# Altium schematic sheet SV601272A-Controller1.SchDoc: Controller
size 431 x 279 mm; Date: Not shown in title block; ApprovedBy: Not shown in title block; CheckedBy: Not shown in title block; Author: Not shown in title block; CompanyName: Not shown in title block; Engineer: Not shown in title block; Organization: Not shown in title block; Address1: Not shown in title block; Address2: Not shown in title block; Address3: Not shown in title block; Address4: Not shown in title block; DocumentNumber: 4; Revision: Use project parameter SCH_Rev; SheetNumber: 4; SheetTotal: 11; PageSetup: Record=PageOptions¦CenterHorizontal=True¦CenterVertical=True¦PrintScale=1.00¦XCorrection=1.00¦YCorrection=1.00¦PrintKind=0¦BorderSize=5000000¦LeftOffset=0¦BottomOffset=0¦Orientation=2¦PaperLength=1000¦PaperWidth=1000¦Scale=100¦PaperSource=15¦PrintQuality=600¦MediaType=1¦DitherType=10¦PaperKind=Letter¦PrintScaleMode=1
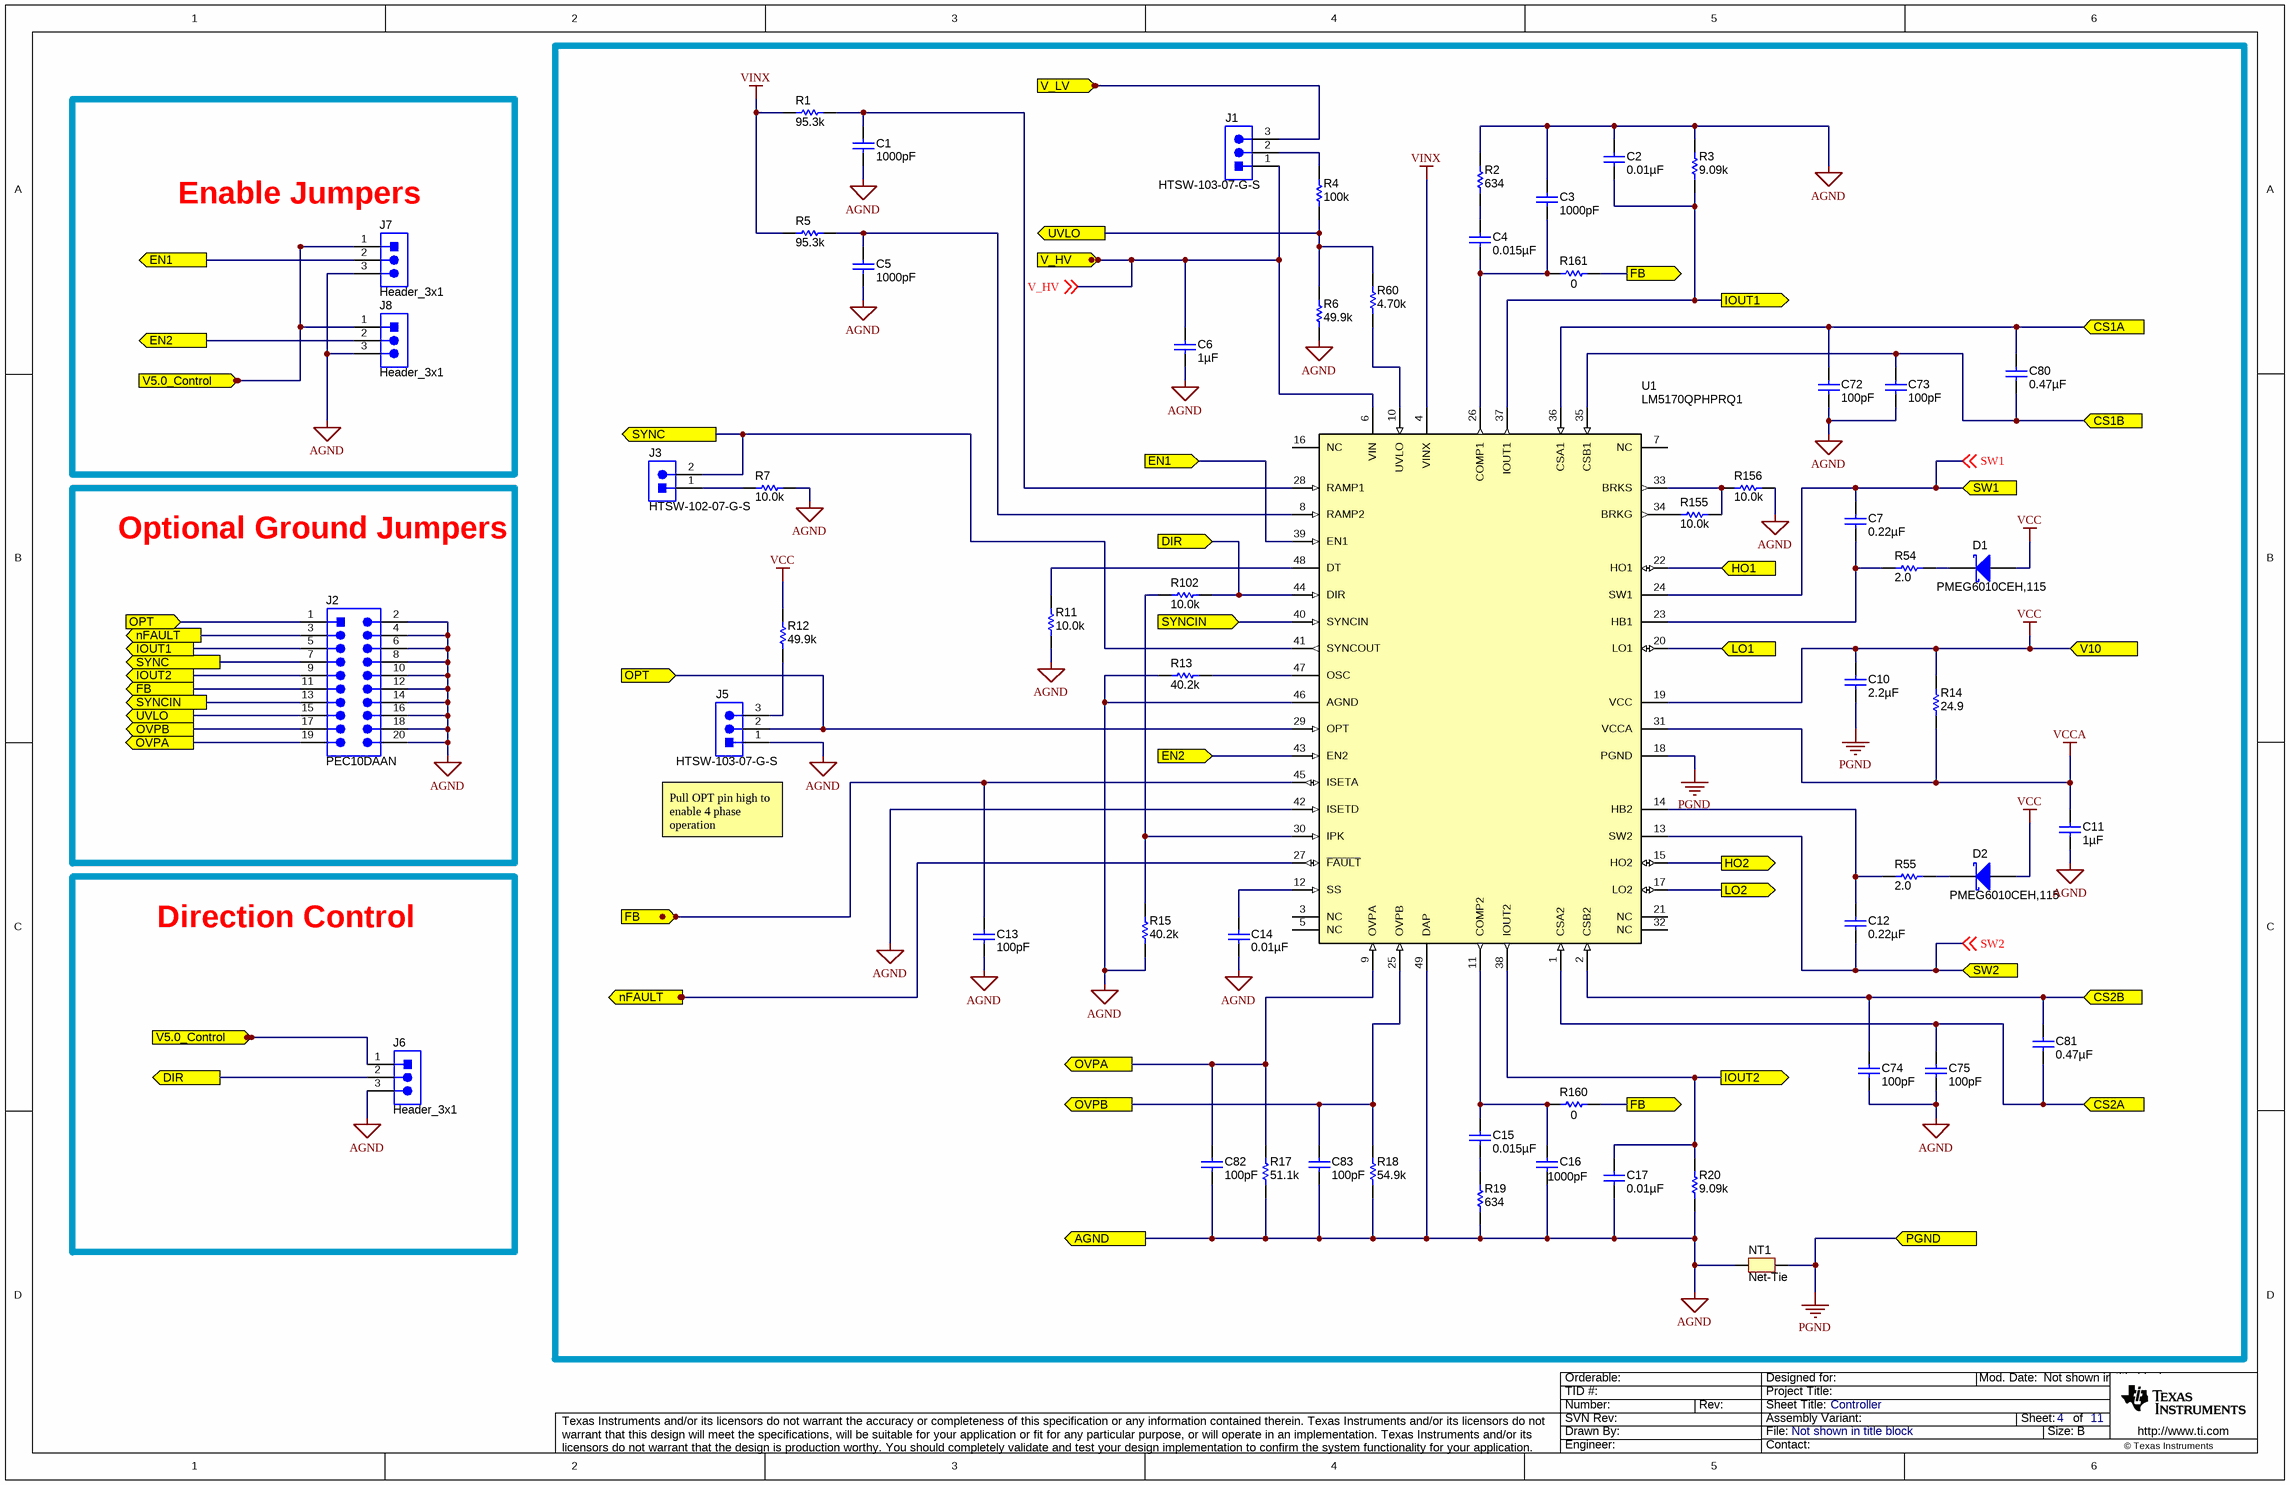
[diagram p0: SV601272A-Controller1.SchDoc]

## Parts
C1  ValueDisplayed: 1000pF  [0603L]  (hidden comment: C1608C0G2A102J080AA)
C2  ValueDisplayed: 0.01µF  [0603L]  (hidden comment: 06031C103KAT2A)
C3  ValueDisplayed: 1000pF  [0603L]  (hidden comment: C1608C0G2A102J080AA)
C4  ValueDisplayed: 0.015µF  [0603L]  (hidden comment: GRM188R71E153KA01D)
C5  ValueDisplayed: 1000pF  [0603L]  (hidden comment: C1608C0G2A102J080AA)
C6  ValueDisplayed: 1µF  [0805_HV]  (hidden comment: C2012X7S2A105K125AB)
C7  ValueDisplayed: 0.22µF  [0603L]  (hidden comment: C1608X7R1H224K080AB)
C10  ValueDisplayed: 2.2µF  [0805_HV]  (hidden comment: C2012X7R1C225K125AB)
C11  ValueDisplayed: 1µF  [0603L]  (hidden comment: GRM188R71E105KA12D)
C12  ValueDisplayed: 0.22µF  [0603L]  (hidden comment: C1608X7R1H224K080AB)
C13  ValueDisplayed: 100pF  [0603L]  (hidden comment: C0603C101J5GACTU)
C14  ValueDisplayed: 0.01µF  [0603L]  (hidden comment: 06031C103KAT2A)
C15  ValueDisplayed: 0.015µF  [0603L]  (hidden comment: GRM188R71E153KA01D)
C16  ValueDisplayed: 1000pF  [0603L]  (hidden comment: C1608C0G2A102J080AA)
C17  ValueDisplayed: 0.01µF  [0603L]  (hidden comment: 06031C103KAT2A)
C72  ValueDisplayed: 100pF  [0603L]  (hidden comment: C0603C101J5GACTU)
C73  ValueDisplayed: 100pF  [0603L]  (hidden comment: C0603C101J5GACTU)
C74  ValueDisplayed: 100pF  [0603L]  (hidden comment: C0603C101J5GACTU)
C75  ValueDisplayed: 100pF  [0603L]  (hidden comment: C0603C101J5GACTU)
C80  ValueDisplayed: 0.47µF  [0603L]  (hidden comment: GRM188R71C474KA88D)
C81  ValueDisplayed: 0.47µF  [0603L]  (hidden comment: GRM188R71C474KA88D)
C82  ValueDisplayed: 100pF  [0603L]  (hidden comment: C0603C101J5GACTU)
C83  ValueDisplayed: 100pF  [0603L]  (hidden comment: C0603C101J5GACTU)
D1  PMEG6010CEH,115  [SOD-123F]
D2  PMEG6010CEH,115  [SOD-123F]
J1  HTSW-103-07-G-S  [Samtec_HTSW-103-07-G-S]
J2  PEC10DAAN  [SULLINS_PEC10DAAN]
J3  HTSW-102-07-G-S  [Samtec_HTSW-102-07-G-S]
J5  HTSW-103-07-G-S  [Samtec_HTSW-103-07-G-S]
J6  Header_3x1  [Samtec_HTSW-103-07-G-S]
J7  Header_3x1  [Samtec_HTSW-103-07-G-S]
J8  Header_3x1  [Samtec_HTSW-103-07-G-S]
NT1  Net-Tie  [Net-Tie_10mil]  (net tie, no BOM)
R1  ValueDisplayed: 95.3k  [0603L]  (hidden comment: CRCW060395K3FKEA)
R2  ValueDisplayed: 634  [0603L]  (hidden comment: CRCW0603634RFKEA)
R3  ValueDisplayed: 9.09k  [0603L]  (hidden comment: CRCW06039K09FKEA)
R4  ValueDisplayed: 100k  [0603]  (hidden comment: CRCW0603100KFKEA)
R5  ValueDisplayed: 95.3k  [0603L]  (hidden comment: CRCW060395K3FKEA)
R6  ValueDisplayed: 49.9k  [0603]  (hidden comment: ERJ-3EKF4992V)
R7  ValueDisplayed: 10.0k  [0603L]  (hidden comment: CRCW060310K0FKEA)
R11  ValueDisplayed: 10.0k  [0603L]  (hidden comment: CRCW060310K0FKEA)
R12  ValueDisplayed: 49.9k  [0603L]  (hidden comment: CRCW060349K9FKEA)
R13  ValueDisplayed: 40.2k  [0603L]  (hidden comment: CRCW060340K2FKEA)
R14  ValueDisplayed: 24.9  [0805L]  (hidden comment: CRCW080524R9FKEA)
R15  ValueDisplayed: 40.2k  [0603]  (hidden comment: ERJ-3EKF4022V)
R17  ValueDisplayed: 51.1k  [0603L]  (hidden comment: CRCW060351K1FKEA)
R18  ValueDisplayed: 54.9k  [0603L]  (hidden comment: CRCW060354K9FKEA)
R19  ValueDisplayed: 634  [0603L]  (hidden comment: CRCW0603634RFKEA)
R20  ValueDisplayed: 9.09k  [0603L]  (hidden comment: CRCW06039K09FKEA)
R54  ValueDisplayed: 2.0  [0805_HV]  (hidden comment: CRCW08052R00JNEA)
R55  ValueDisplayed: 2.0  [0805_HV]  (hidden comment: CRCW08052R00JNEA)
R60  ValueDisplayed: 4.70k  [0603]  (hidden comment: RC0603FR-074K7L)
R102  ValueDisplayed: 10.0k  [0603L]  (hidden comment: CRCW060310K0FKEA)
R155  ValueDisplayed: 10.0k  [0603]  (hidden comment: ERJ-3EKF1002V)
R156  ValueDisplayed: 10.0k  [0603]  (hidden comment: ERJ-3EKF1002V)
R160  ValueDisplayed: 0  [0603]  (hidden comment: Resistor)
R161  ValueDisplayed: 0  [0603]  (hidden comment: Resistor)
U1  LM5170QPHPRQ1  [PHP0048D_L]

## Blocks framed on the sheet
Enable Jumpers: J7 J8
Optional Ground Jumpers: J2
Direction Control: J6

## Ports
AGND, CS1A, CS1B, CS2A, CS2B, DIR, EN1, EN2, FB, HO1, HO2, IOUT1, IOUT2, LO1, LO2, nFAULT, OPT, OVPA, OVPB, PGND, SW1, SW2, SYNC, SYNCIN, UVLO, V5.0_Control, V10, V_HV, V_LV

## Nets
AGND: C1.2 C2.1 C3.1 C5.2 C6.2 C11.2 C13.2 C14.2 C16.2 C17.2 C72.2 C73.2 C74.2 C75.2 C82.2 C83.2 J2.2 J2.4 J2.6 J2.8 J2.10 J2.12 J2.14 J2.16 J2.18 J2.20 J5.1 J6.3 J7.3 J8.3 NT1.1 R2.2 R3.2 R6.1 R7.2 R11.1 R13.1 R15.1 R17.1 R18.1 R19.1 R20.1 R156.1 U1.42(ISETD) U1.46(AGND) U1.49(DAP) ; port AGND
PGND: C10.2 NT1.2 U1.18(PGND) ; port PGND
VCC: C10.1 D1.2(A) D2.2(A) R12.2 R14.2 U1.19(VCC) ; port V10
VCCA: C11.1 R14.1 U1.31(VCCA)
VINX: R1.1 R5.1 U1.4(VINX)
CS1A: C72.1 C80.1 U1.36(CSA1) ; port CS1A
CS1B: C73.1 C80.2 U1.35(CSB1) ; port CS1B
CS2A: C75.1 C81.2 U1.1(CSA2) ; port CS2A
CS2B: C74.1 C81.1 U1.2(CSB2) ; port CS2B
DIR: J6.2 R102.2 U1.44(DIR) ; port DIR
EN1: J7.2 U1.39(EN1) ; port EN1
EN2: J8.2 U1.43(EN2) ; port EN2
FB: C13.1 J2.11 R160.2 R161.2 U1.45(ISETA) ; port FB
HO1: U1.22(HO1) ; port HO1
HO2: U1.15(HO2) ; port HO2
IOUT1: C2.2 J2.5 R3.1 U1.37(IOUT1) ; port IOUT1
IOUT2: C17.1 J2.9 R20.2 U1.38(IOUT2) ; port IOUT2
LO1: U1.20(LO1) ; port LO1
LO2: U1.17(LO2) ; port LO2
nFAULT: J2.3 U1.27(~{FAULT}) ; port nFAULT
OPT: J2.1 J5.2 U1.29(OPT) ; port OPT
OVPA: C82.1 J2.19 R17.2 U1.9(OVPA) ; port OVPA
OVPB: C83.1 J2.17 R18.2 U1.25(OVPB) ; port OVPB
SW1: C7.1 U1.24(SW1) ; off-sheet SW1, port SW1
SW2: C12.2 U1.13(SW2) ; off-sheet SW2, port SW2
SYNC: J2.7 J3.2 U1.41(SYNCOUT) ; port SYNC
SYNCIN: J2.13 U1.40(SYNCIN) ; port SYNCIN
UVLO: J2.15 R4.1 R6.2 R60.2 ; port UVLO
V5.0_Control: J6.1 J7.1 J8.1 ; port V5.0_Control
V_HV: C6.1 J1.1 U1.6(VIN) ; off-sheet V_HV, port V_HV
V_LV: J1.3 ; port V_LV
NetC1_1: C1.1 R1.2 U1.28(RAMP1)
NetC3_2: C3.2 C4.2 R161.1 U1.26(COMP1)
NetC4_1: C4.1 R2.1
NetC5_1: C5.1 R5.2 U1.8(RAMP2)
NetC7_2: C7.2 R54.1 U1.23(HB1)
NetC12_1: C12.1 R55.1 U1.14(HB2)
NetC14_1: C14.1 U1.12(SS)
NetC15_1: C15.1 C16.1 R160.1 U1.11(COMP2)
NetC15_2: C15.2 R19.2
NetD1_1: D1.1(K) R54.2
NetD2_1: D2.1(K) R55.2
NetJ1_2: J1.2 R4.2
NetJ3_1: J3.1 R7.1
NetJ5_3: J5.3 R12.1
NetR11_2: R11.2 U1.48(DT)
NetR13_2: R13.2 U1.47(OSC)
NetR15_2: R15.2 R102.1 U1.30(IPK)
NetR60_1: R60.1 U1.10(UVLO)
NetR155_1: R155.1 R156.2 U1.33(BRKS)
NetR155_2: R155.2 U1.34(BRKG)

Not connected (* = marked no-connect by the designer): U1 3(NC) 5(NC) 7(NC) 16(NC) 21(NC) 32(NC)

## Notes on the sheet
- (near J5) Pull OPT pin high to enable 4 phase operation

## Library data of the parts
C1 C3 C5 C16 = C1608C0G2A102J080AA: CAP, CERM, 1000 pF, 100 V, +/- 5%, C0G/NP0, 0603; Manufacturer: TDK; Polarized: N; CompType: Capacitor; Value: 1000pF; U/M: EA; Cap_F: 0.000000001; Tolerance_%: 5; ESR_ohm: 0.0589; Value1: 0.0589 ohm; VDC_V: 100; Value2: 100V; TaMin_C: -55; TaMax_C: 125; Cap_Case: 0603; AEC Category: Q200
C2 C14 C17 = 06031C103KAT2A: CAP, CERM, 0.01 µF, 100 V, +/- 10%, X7R, 0603; Manufacturer: AVX; Polarized: N; CompType: Capacitor; Value: 0.01uF; U/M: EA; Cap_F: 0.00000001; Tolerance_%: 10; ESR_ohm: 0.098; Value1: 0.098 ohm; VDC_V: 100; Value2: 100V; TaMin_C: -55; TaMax_C: 125; Cap_Case: 0603
C4 C15 = GRM188R71E153KA01D: CAP, CERM, 0.015 µF, 25 V, +/- 10%, X7R, 0603; Manufacturer: MuRata; Polarized: N; CompType: Capacitor; Value: 0.015uF; U/M: EA; Cap_F: 0.000000015; Tolerance_%: 10; Value1: Unknown; VDC_V: 25; Value2: 25V; TaMin_C: -55; TaMax_C: 125; Cap_Case: 0603
C6 = C2012X7S2A105K125AB: CAP, CERM, 1 µF, 100 V, +/- 10%, X7S, 0805; Manufacturer: TDK; Polarized: N; CompType: Capacitor; Value: 1uF; U/M: EA; Cap_F: 0.000001; Tolerance_%: 10; Value1: Unknown; VDC_V: 100; Value2: 100V; TaMin_C: -55; TaMax_C: 125; Cap_Case: 0805; AEC Category: Q200
C7 C12 = C1608X7R1H224K080AB: CAP, CERM, 0.22 µF, 50 V, +/- 10%, X7R, 0603; Manufacturer: TDK; Polarized: N; CompType: Capacitor; Value: 0.22uF; U/M: EA; Cap_F: 0.00000022; Tolerance_%: 10; Value1: Unknown; VDC_V: 50; Value2: 50V; TaMin_C: -55; TaMax_C: 125; Cap_Case: 0603
C10 = C2012X7R1C225K125AB: CAP, CERM, 2.2 µF, 16 V, +/- 10%, X7R, 0805; Manufacturer: TDK; CompType: Capacitor; Value: 2.2uF; U/M: EA; Tolerance_%: 10; VDC_V: 16; Polarized: N; Cap_F: 0.0000022; ESR_ohm: 0.0049; Value1: 0.0049 ohm; Value2: 16V; TaMin_C: -55; TaMax_C: 125; Cap_Case: 0805; AEC Category: Q200
C11 = GRM188R71E105KA12D: CAP, CERM, 1 µF, 25 V, +/- 10%, X7R, 0603; Manufacturer: MuRata; Polarized: N; CompType: Capacitor; Value: 1uF; U/M: EA; Cap_F: 0.000001; Tolerance_%: 10; Value1: Unknown; VDC_V: 25; Value2: 25V; TaMin_C: -55; TaMax_C: 125; Cap_Case: 0603
C13 = C0603C101J5GACTU: CAP, CERM, 100 pF, 50 V, +/- 5%, C0G/NP0, 0603; Manufacturer: Kemet; Polarized: N; CompType: Capacitor; Value: 100pF; U/M: EA; Cap_F: 0.0000000001; Tolerance_%: 5; Value1: Unknown; VDC_V: 50; Value2: 50V; TaMin_C: -55; TaMax_C: 125; Cap_Case: 0603; AEC Category: Q200; SizeArea_mm2: 1.28; SizeAreaWB_mm2: 4.68; SizeX_mm: 1.6; SizeY_mm: 0.8; SizeZ_mm: 1
C72-C75 C82 C83 = C0603C101J5GACTU: CAP, CERM, 100 pF, 50 V, +/- 5%, C0G/NP0, 0603; Manufacturer: Kemet; Polarized: N; CompType: Capacitor; Value: 100pF; U/M: EA; Cap_F: 0.0000000001; Tolerance_%: 5; Value1: Unknown; VDC_V: 50; Value2: 50V; TaMin_C: -55; TaMax_C: 125; Cap_Case: 0603; AEC Category: Q200
C80 C81 = GRM188R71C474KA88D: CAP, CERM, 0.47 µF, 16 V, +/- 10%, X7R, 0603; Manufacturer: MuRata; Polarized: N; CompType: Capacitor; Value: 0.47uF; U/M: EA; Cap_F: 0.00000047; Tolerance_%: 10; Value1: Unknown; VDC_V: 16; Value2: 16V; TaMin_C: -55; TaMax_C: 125; Cap_Case: 0603; AEC Category: Q200
D1 D2 = PMEG6010CEH,115: Diode, Schottky, 60 V, 1 A, SOD-123F; Manufacturer: NXP Semiconductor; U/M: EA; Vf_V: 0.57; Value: 60V; Value1: 1A; Value2: 0.57V; Io_A: 1; Vr_V: 60; TJmax_C: 150
J1 J5 = HTSW-103-07-G-S: Header, 100mil, 3x1, Gold, TH; Manufacturer: Samtec; SymbolCreator: a0799628; U/M: EA
J2 = CMP-0054623-1: Header, 2.54mm, 10x2, Tin, TH; Manufacturer: Sullins Connector Solutions; CNHeader: TRUE; Current_A: 3A; Green_Lifecycle: Not Set; Shrouded: N; Gender: Male; Green_REACh: Incomplete; Row_Count: 2; RowSpacing_mm: 2.54; CT: FALSE; Cert_UL: Y
J3 = HTSW-102-07-G-S: Header, 100mil, 2x1, Gold, TH; Manufacturer: Samtec; SymbolCreator: a0412235; U/M: EA
J6-J8 = CMP-0075484-1: Header, 100mil, 3x1, Gold, TH; PartNumber: HTSW-103-07-G-S; Manufacturer: Samtec; CNHeader: True; CT: False; Green_Lifecycle: Active; Green_REACh: Passed
NT1 = Net-Tie: Single point connection between nets.; SymbolCreator: codlsc
R1 R5 = CRCW060395K3FKEA: RES, 95.3 k, 1%, 0.1 W, 0603; Manufacturer: Vishay-Dale; CompType: Resistor; Value: 95.3k; Res_ohm: 95300; Value_Code: 95k3; Tolerance_%: 1; Power_W: 0.1; Value2: 0.1W; VDC_V: 75; TempCo: 100 ppm/C; EIA_Code: E96; U/M: EA
R2 R19 = CRCW0603634RFKEA: RES, 634, 1%, 0.1 W, 0603; Manufacturer: Vishay-Dale; CompType: Resistor; Value: 634; Value_Code: 634R; Tolerance_%: 1; Power_W: 0.1; Value2: 0.1W; VDC_V: 75; TempCo: 100 ppm/C; EIA_Code: E96; U/M: EA
R3 R20 = CRCW06039K09FKEA: RES, 9.09 k, 1%, 0.1 W, 0603; Manufacturer: Vishay-Dale; CompType: Resistor; Value: 9.09k; Res_ohm: 9090; Value_Code: 9k09; Tolerance_%: 1; Power_W: 0.1; Value2: 0.1W; VDC_V: 75; TempCo: 100 ppm/C; EIA_Code: E96; U/M: EA
R4 = CMP-0021990-4: RES, 100 k, 1%, 0.1 W, AEC-Q200 Grade 0, 0603; Manufacturer: Vishay-Dale; Power_W: 100mW; TempCo: 100 ppm/C; Value: 100k; EIA_Code: E96; SizeX_mm: 1.6; SizeY_mm: 0.8; SizeZ_mm: 1; Value2: 0.1W; SizeArea_mm2: 1.28; CompType: Resistor; AEC Qualified: Y; VDC_V: 75V; AEC Category: Q200; AEC Grade: 0
R6 = CMP-0022705-3: RES, 49.9 k, 1%, 0.1 W, AEC-Q200 Grade 0, 0603; Manufacturer: Panasonic; Power_W: 100mW; TempCo: 100 ppm/C; Value_Code: 49k9; U/M: EA; Value: 49.9k; EIA_Code: E96; SizeX_mm: 1.6; SizeY_mm: 0.8; SizeZ_mm: 1; Value2: 0.1W; SizeArea_mm2: 1.28; CompType: Resistor; AEC Qualified: Y; VDC_V: 75V; AEC Grade: 0; AEC Category: Q200
R7 R102 = CRCW060310K0FKEA: RES, 10.0 k, 1%, 0.1 W, 0603; Manufacturer: Vishay-Dale; CompType: Resistor; Value: 10.0k; Res_ohm: 10000; Value_Code: 10k0; Tolerance_%: 1; Power_W: 0.1; Value2: 0.1W; VDC_V: 75; TempCo: 100 ppm/C; EIA_Code: E96; U/M: EA
R11 = CRCW060310K0FKEA: RES, 10.0 k, 1%, 0.1 W, 0603; Manufacturer: Vishay-Dale; CompType: Resistor; Value: 10.0k; Res_ohm: 10000; Value_Code: 10k0; Tolerance_%: 1; Power_W: 0.1; Value2: 0.1W; VDC_V: 75; TempCo: 100 ppm/C; EIA_Code: E96; U/M: EA; SizeArea_mm2: 1.28; SizeX_mm: 1.6; SizeY_mm: 0.8; AEC Category: Q200
R12 = CRCW060349K9FKEA: RES, 49.9 k, 1%, 0.1 W, 0603; Manufacturer: Vishay-Dale; CompType: Resistor; Value: 49.9k; Res_ohm: 49900; Value_Code: 49k9; Tolerance_%: 1; Power_W: 0.1; Value2: 0.1W; VDC_V: 75; TempCo: 100 ppm/C; EIA_Code: E96; U/M: EA
R13 = CRCW060340K2FKEA: RES, 40.2 k, 1%, 0.1 W, 0603; Manufacturer: Vishay-Dale; CompType: Resistor; Value: 40.2k; Res_ohm: 40200; Value_Code: 40k2; Tolerance_%: 1; Power_W: 0.1; Value2: 0.1W; VDC_V: 75; TempCo: 100 ppm/C; EIA_Code: E96; U/M: EA; SizeArea_mm2: 1.28; SizeX_mm: 1.6; SizeY_mm: 0.8; AEC Category: Q200
R14 = CRCW080524R9FKEA: RES, 24.9, 1%, 0.125 W, 0805; Manufacturer: Vishay-Dale; CompType: Resistor; Value: 24.9; Value_Code: 24R9; Tolerance_%: 1; Power_W: 0.125; Value2: 0.125W; VDC_V: 150; TempCo: 100 ppm/C; EIA_Code: E96; U/M: EA
R15 = CMP-0022700-3: RES, 40.2 k, 1%, 0.1 W, AEC-Q200 Grade 0, 0603; Manufacturer: Panasonic; Power_W: 100mW; TempCo: 100 ppm/C; Value_Code: 40k2; U/M: EA; Value: 40.2k; EIA_Code: E96; SizeX_mm: 1.6; SizeY_mm: 0.8; SizeZ_mm: 1; Value2: 0.1W; SizeArea_mm2: 1.28; CompType: Resistor; AEC Qualified: Y; VDC_V: 75V; AEC Grade: 0; AEC Category: Q200
R17 = CRCW060351K1FKEA: RES, 51.1 k, 1%, 0.1 W, 0603; Manufacturer: Vishay-Dale; CompType: Resistor; Value: 51.1k; Res_ohm: 51100; Value_Code: 51k1; Tolerance_%: 1; Power_W: 0.1; Value2: 0.1W; VDC_V: 75; TempCo: 100 ppm/C; EIA_Code: E96; U/M: EA
R18 = CRCW060354K9FKEA: RES, 54.9 k, 1%, 0.1 W, 0603; Manufacturer: Vishay-Dale; CompType: Resistor; Value: 54.9k; Res_ohm: 54900; Value_Code: 54k9; Tolerance_%: 1; Power_W: 0.1; Value2: 0.1W; VDC_V: 75; TempCo: 100 ppm/C; EIA_Code: E96; U/M: EA
R54 R55 = CRCW08052R00JNEA: RES, 2.0, 5%, 0.125 W, 0805; Manufacturer: Vishay-Dale; CompType: Resistor; Value: 2.0; Res_ohm: 2; Value_Code: 2R00; Tolerance_%: 5; Power_W: 0.125; Value2: 0.125W; VDC_V: 150; TempCo: 200 ppm/C; EIA_Code: E24; U/M: EA; AEC Category: Q200
R60 = CMP-0023153-3: RES, 4.70 k, 1%, 0.1 W, 0603; Manufacturer: Yageo America; Power_W: 100mW; TempCo: 200 ppm/C; Value_Code: 4k70; U/M: EA; Value: 4.70k; Res_ohm: 4.7k; SizeX_mm: 1.6; SizeY_mm: 0.8; SizeZ_mm: 1; Value2: 0.1W; SizeArea_mm2: 1.28; CompType: Resistor; VDC_V: 150V; AEC Category: Q200
R155 R156 = CMP-0022684-3: RES, 10.0 k, 1%, 0.1 W, 0603; Manufacturer: Panasonic; Power_W: 100mW; TempCo: 100 ppm/C; Value_Code: 10k0; U/M: EA; Value: 10.0k; EIA_Code: E96; Res_ohm: 10k; SizeX_mm: 1.6; SizeY_mm: 0.8; SizeZ_mm: 1; Value2: 0.1W; SizeArea_mm2: 1.28; CompType: Resistor; VDC_V: 75V; AEC Category: Q200
R160 R161 = CMP-0025874-3: RES, 0, 5%, 0.1 W, 0603; PartNumber: ERJ-3GEY0R00V; Manufacturer: Panasonic; Value: 0; Value_Code: 0000; Power_W: 100mW; Value2: 0.1W; VDC_V: 50V; TempCo: 600 ppm/C; EIA_Code: E24; U/M: EA; AEC Category: Q200; SizeArea_mm2: 1.28; SizeX_mm: 1.6; SizeY_mm: 0.8; SizeZ_mm: 1
U1 = LM5170QPHPRQ1: Dual Channel 48V-12V Bidirectional Current Controller, PHP0048D; Manufacturer: Texas Instruments; Alternate PartNumber: LM5170QPHPTQ1; SymbolCreator: Altium; CompType: IC; U/M: EA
